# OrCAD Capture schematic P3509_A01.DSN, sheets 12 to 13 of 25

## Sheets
12 0013_USB3.1 HUB: size Custom
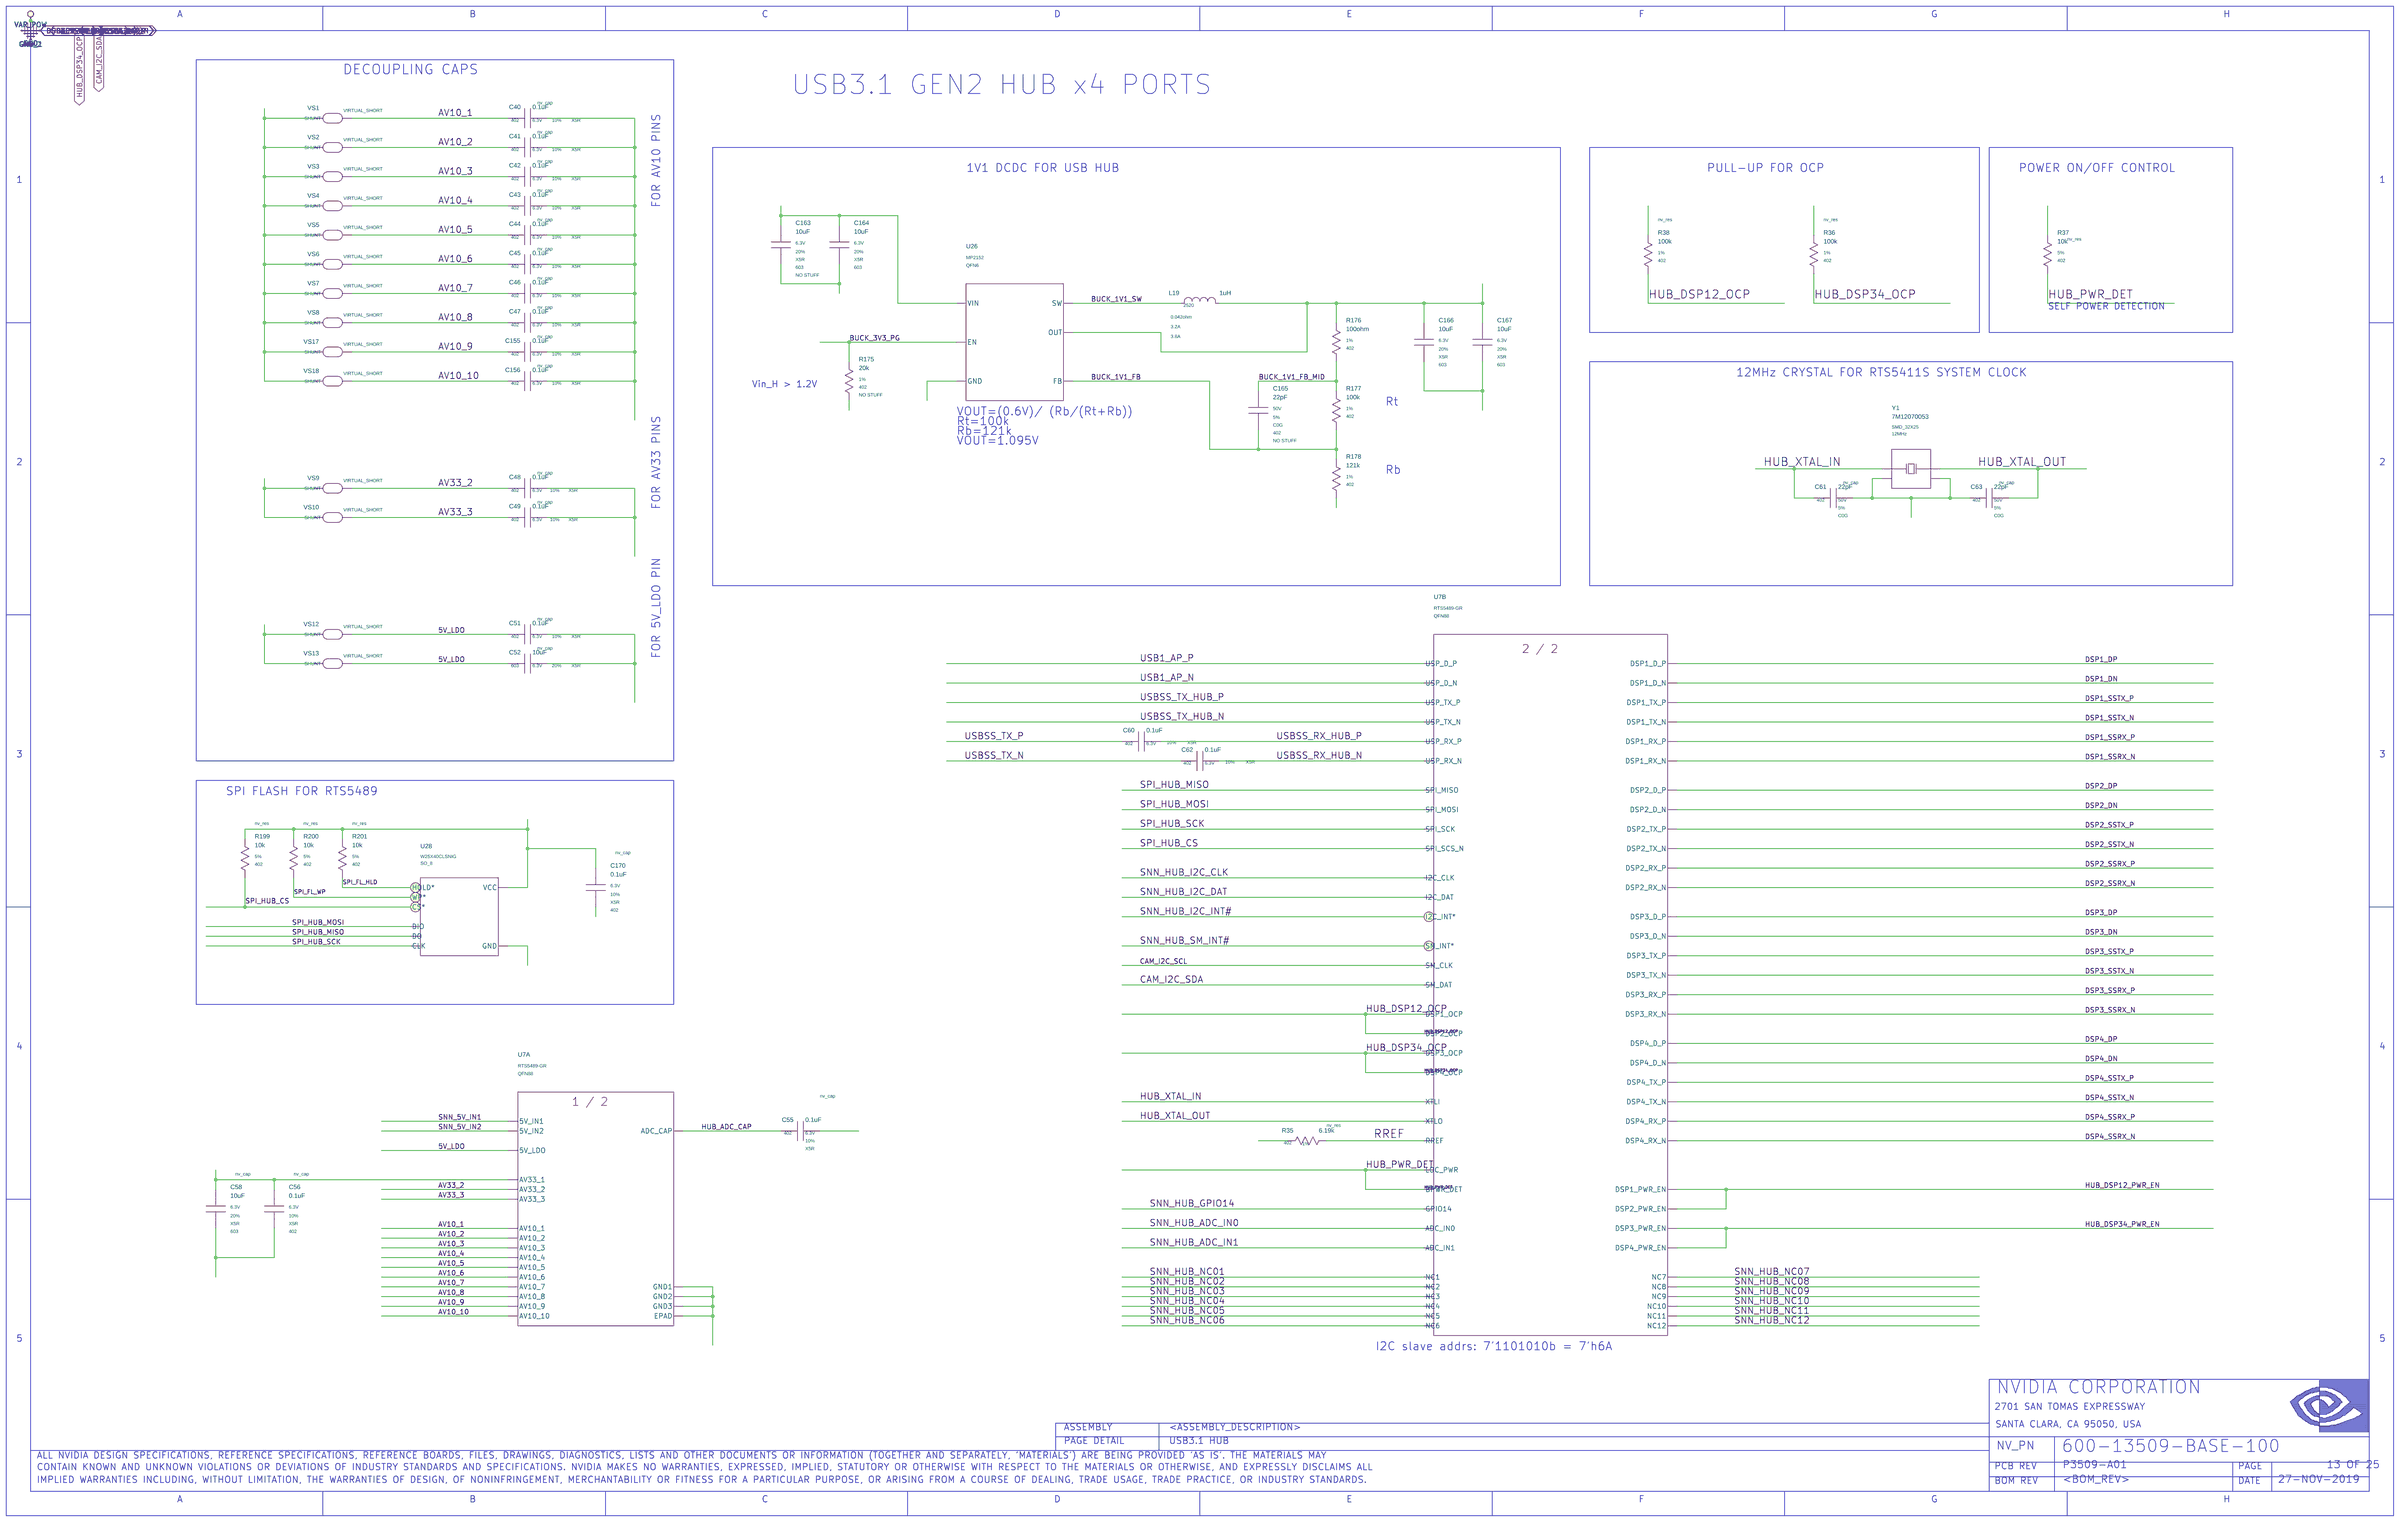
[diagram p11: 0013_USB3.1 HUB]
13 0012_MICRO USB2.0: size Custom
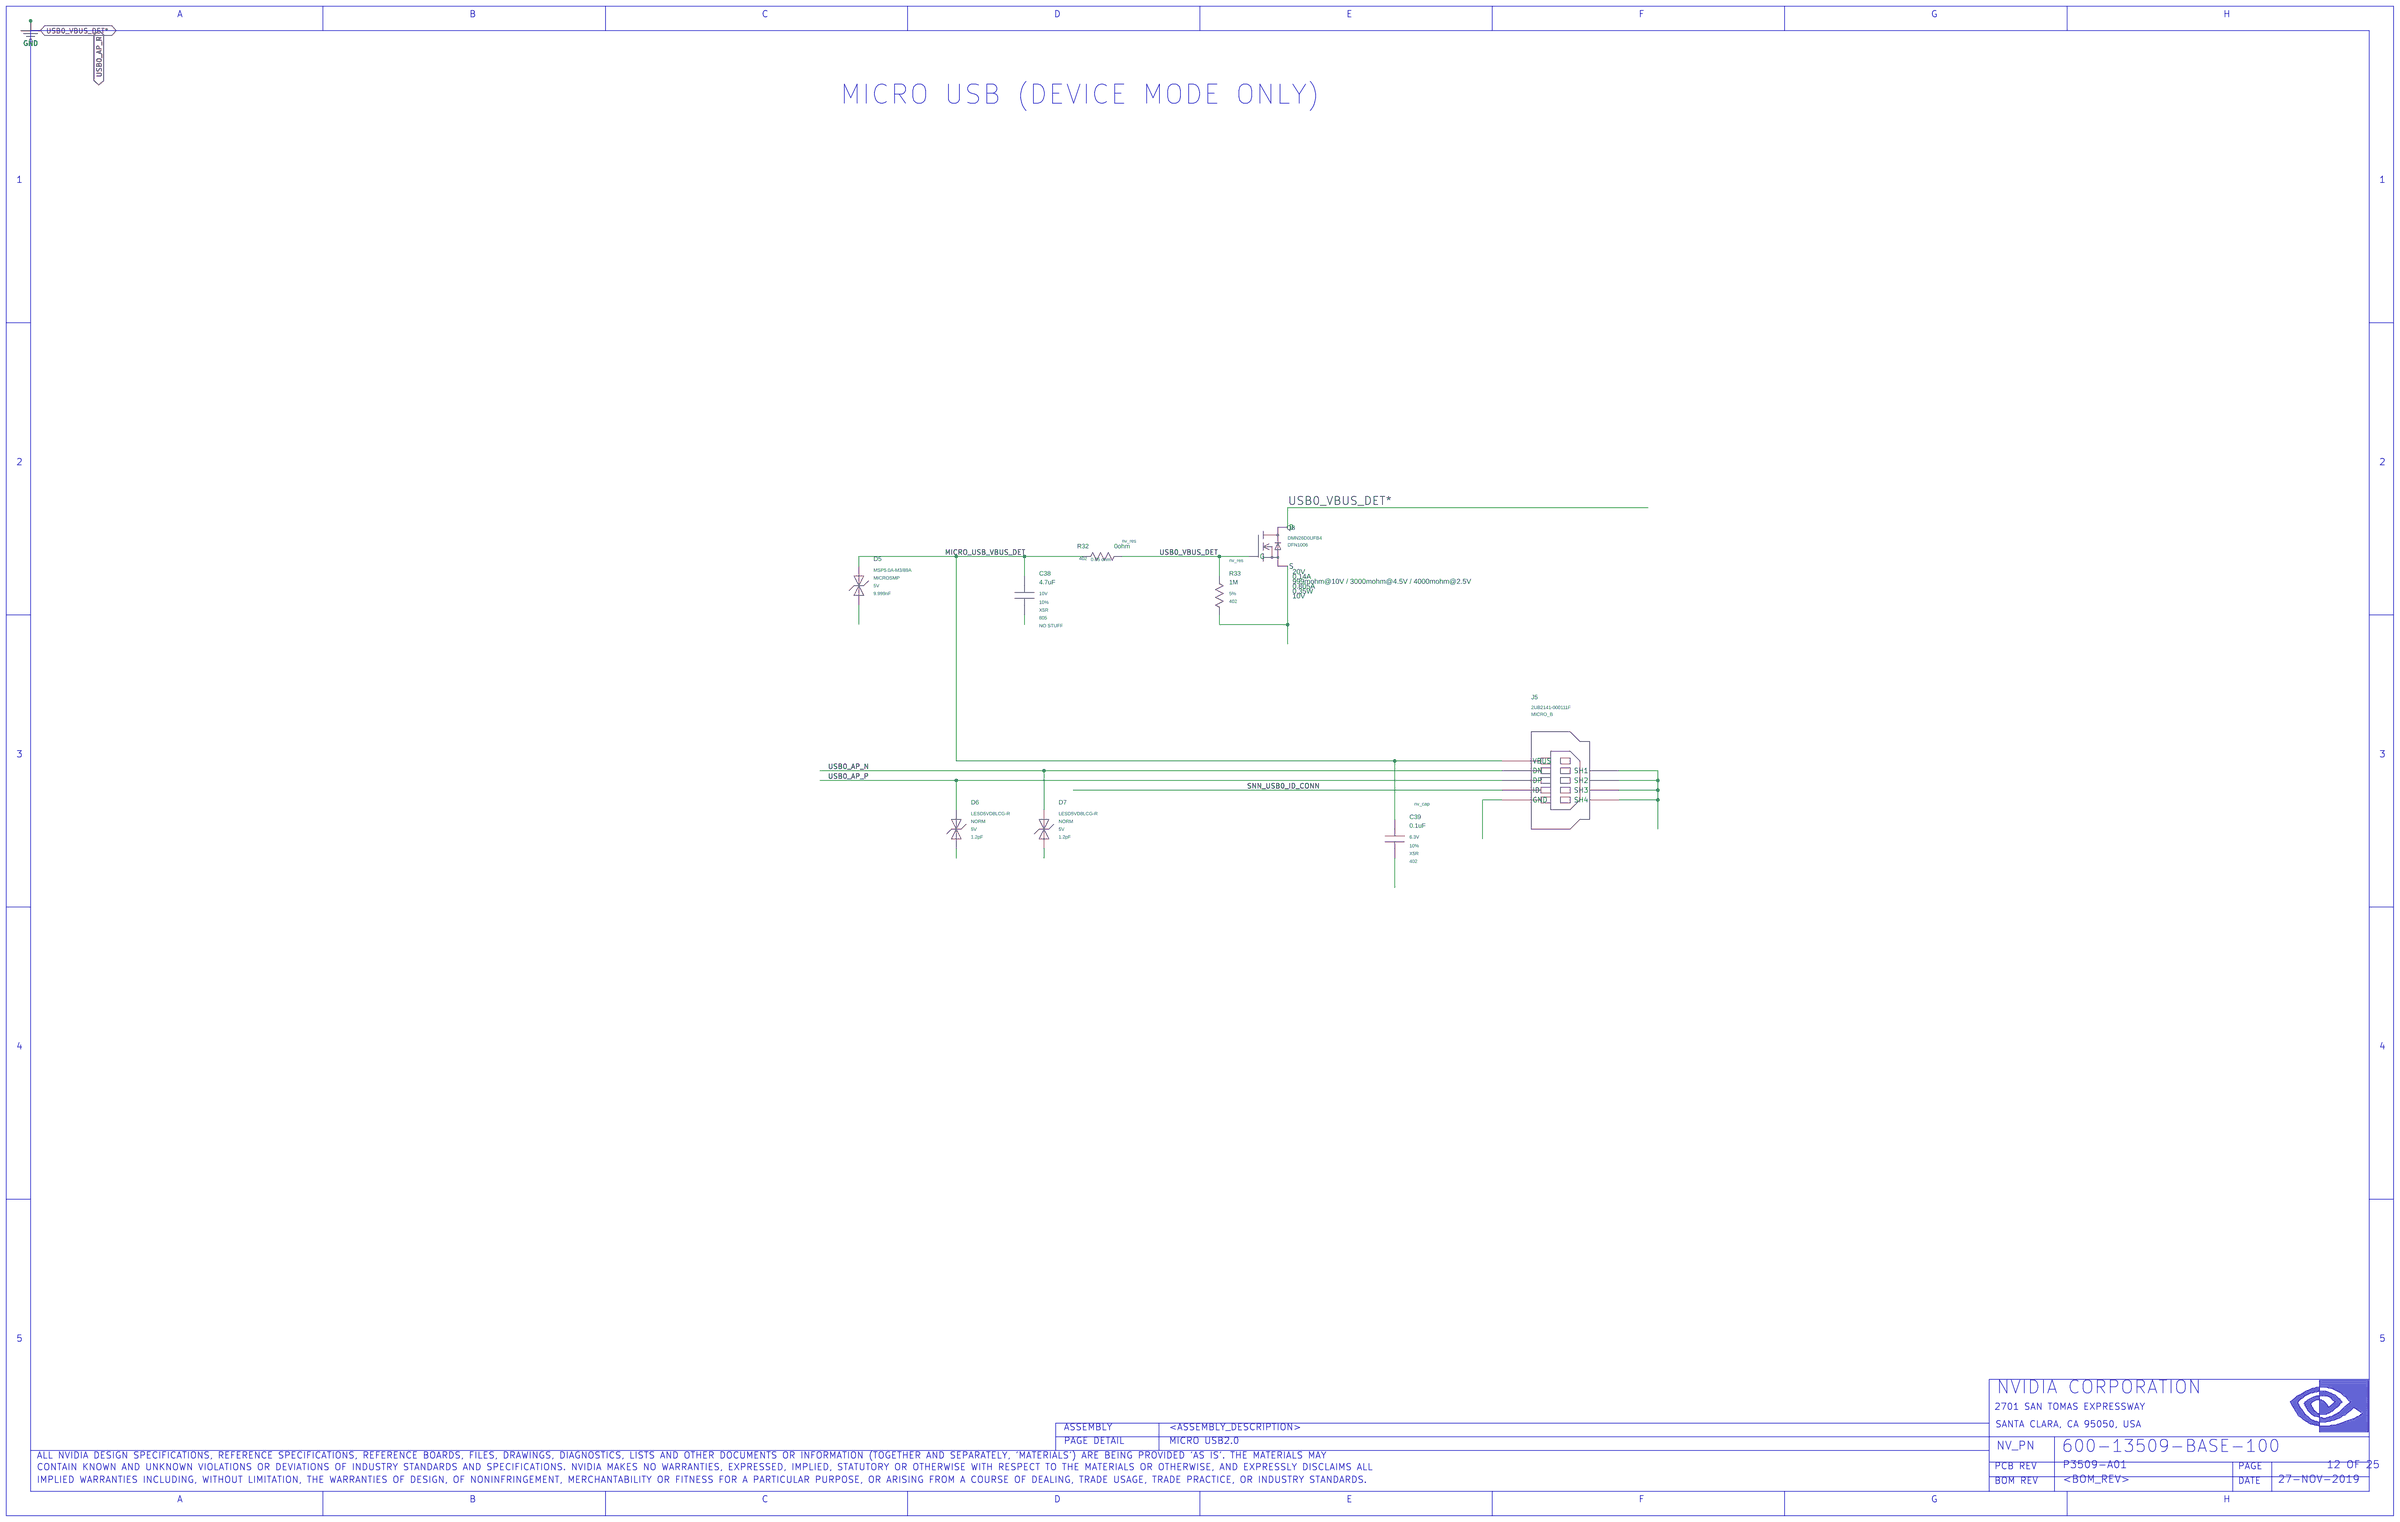
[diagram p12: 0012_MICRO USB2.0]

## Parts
sheet 0012_MICRO USB2.0
C38  4.7uF  [805]
C39  0.1uF  [402]
D5  D_ESD  [DIODE_SMD_025X013]
D6  D_ESD  [DIODE_SMD_010X060]
D7  D_ESD  [DIODE_SMD_010X060]
J5  CON_USB  [CON_USB_005_SMT_RA_080X066]
Q8  Q_FET_N_ENH  [DFET_003_SMD_010X006_B]
R32  0ohm  [402]
R33  1M  [402]
sheet 0013_USB3.1 HUB
C40  0.1uF  [402]
C41  0.1uF  [402]
C42  0.1uF  [402]
C43  0.1uF  [402]
C44  0.1uF  [402]
C45  0.1uF  [402]
C46  0.1uF  [402]
C47  0.1uF  [402]
C48  0.1uF  [402]
C49  0.1uF  [402]
C51  0.1uF  [402]
C52  10uF  [603]
C55  0.1uF  [402]
C56  0.1uF  [402]
C58  10uF  [603]
C60  0.1uF  [402]
C61  22pF  [402]
C62  0.1uF  [402]
C63  22pF  [402]
C155  0.1uF  [402]
C156  0.1uF  [402]
C163  10uF  [603]
C164  10uF  [603]
C165  22pF  [402]
C166  10uF  [603]
C167  10uF  [603]
C170  0.1uF  [402]
L19  1uH  [IND_NONRKO_SMD_025X020]
R35  6.19k  [402]
R36  100k  [402]
R37  10k  [402]
R38  100k  [402]
R175  20k  [402]
R176  100ohm  [402]
R177  100k  [402]
R178  121k  [402]
R199  10k  [402]
R200  10k  [402]
R201  10k  [402]
U7  U_USB_HUB_RTS5489  [QFN088Q_P040_0100_T069X069]  (sections A,B)
U26  0.6V  [DFN06_P050_016X012]
U28  U_MEM_FL_SER_512KX8  [SO08_048X038]
VS1  VIRTUAL_SHORT  [VIRTUAL_SHORT]
VS2  VIRTUAL_SHORT  [VIRTUAL_SHORT]
VS3  VIRTUAL_SHORT  [VIRTUAL_SHORT]
VS4  VIRTUAL_SHORT  [VIRTUAL_SHORT]
VS5  VIRTUAL_SHORT  [VIRTUAL_SHORT]
VS6  VIRTUAL_SHORT  [VIRTUAL_SHORT]
VS7  VIRTUAL_SHORT  [VIRTUAL_SHORT]
VS8  VIRTUAL_SHORT  [VIRTUAL_SHORT]
VS9  VIRTUAL_SHORT  [VIRTUAL_SHORT]
VS10  VIRTUAL_SHORT  [VIRTUAL_SHORT]
VS12  VIRTUAL_SHORT  [VIRTUAL_SHORT]
VS13  VIRTUAL_SHORT  [VIRTUAL_SHORT]
VS17  VIRTUAL_SHORT  [VIRTUAL_SHORT]
VS18  VIRTUAL_SHORT  [VIRTUAL_SHORT]
Y1  12MHz  [XTAL_SMD_4_032X025_D]

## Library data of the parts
C38 = C#1_v2: ASSEMBLY: MICRO_USB; CDS_LIB: discrete; CDS_PART_NAME: C_0805-4.7UF,X5R,10%,10V,039-0152-000; CDS_PHYS_PART_NAME: C_0805-4.7UF,X5R,10%,10V,039-0152-000-039-0152-000,4.7UF; CDS_SEC: 1; CHIPS_PART_NAME: C; DEVICE_TYPENAME: C_0805-47UFX5R1010V039-0152-000-039-0152-00047UF; DRAWING: #NAME?; MAT: X5R; MAX_VOLTAGE: 10V; NV_PN: 039-0152-000; PATH: I14; PHYS_PAGE: 12; ROT: 0; SEC: 1; SIGNAL_MODEL: nv_cap; SKU: NO STUFF; TOL: 10%; VER: 1; XY: (-6900,4600)
C39 = C#1_v2: ASSEMBLY: USBC_PWR; CDS_LIB: discrete; CDS_PART_NAME: C_0402-0.1UF,X5R,10%,6.3V,039-0007-000; CDS_PHYS_PART_NAME: C_0402-0.1UF,X5R,10%,6.3V,039-0007-000-0.1UF,039-0007-000; CDS_SEC: 1; CHIPS_PART_NAME: C; DEVICE_TYPENAME: C_0402-01UFX5R1063V039-0007-000-01UF039-0007-000; DRAWING: #NAME?; MAT: X5R; MAX_VOLTAGE: 6.3V; NV_PN: 039-0007-000; PATH: I20; PHYS_PAGE: 12; ROT: 0; SEC: 1; SIGNAL_MODEL: nv_cap; TOL: 10%; VER: 1; XY: (-5000,3350)
D5 = D_ESD: ASSEMBLY: MICRO_USB; BREAKDOWN_VOLTAGE_MIN_TYP: 6.4V; CAPACITANCE_MAX_TYP: 9.999nF; CDS_LIB: discrete; CDS_PART_NAME: D_ESD_MICROSMP-MSP5.0A-M3/89A,1 LINE,UNI-DIRECTIONAL,5V,100UA,6.4V,9.2V@16.3A,9.999NF,090-0233-000; CDS_PHYS_PART_NAME: D_ESD_MICROSMP-MSP5.0A-M3/89A,1 LINE,UNI-DIRECTIONAL,5V,100UA,6.4V,9.2V@16.3A,9.999NF,090-0233-000-090-0233-000; CDS_SEC: 1; CLAMPING_VOLTAGE: 9.2V@16.3A; CONFIGURATION: 1 Line; DEVICE_TYPENAME: D_ESD_MICROSMP-MSP50A-M389A1LINEUNI-DIRECTIONAL5V100UA64V92V163A9999NF090-0233-000-090-0233-000; DRAWING: #NAME?; MAX_REVERSE_LEAKAGE_CURRENT: 100uA; MAX_REVERSE_VOLTAGE: 5V; NV_NAME: MSP5.0A-M3/89A; NV_PN: 090-0233-000; PACK_TYPE: MICROSMP; PATH: I25; PHYS_PAGE: 12; POLARITY: Uni-Directional; ROT: 0; SEC: 1; VER: 2; XY: (-7750,4650)
D6 = D_ESD: ASSEMBLY: MICRO_USB; BREAKDOWN_VOLTAGE_MIN_TYP: 5.5V; CAPACITANCE_MAX_TYP: 1.2pF; CDS_LIB: discrete; CDS_PART_NAME: D_ESD_NORM-LESD5VD8LCG-R,1 LINE,BI-DIRECTIONAL,5V,0.05UA,5.5V,10V@2A,1.2PF,090-0172-000; CDS_PHYS_PART_NAME: D_ESD_NORM-LESD5VD8LCG-R,1 LINE,BI-DIRECTIONAL,5V,0.05UA,5.5V,10V@2A,1.2PF,090-0172-000-090-0172-000; CDS_SEC: 1; CLAMPING_VOLTAGE: 10V@2A; CONFIGURATION: 1 Line; DEVICE_TYPENAME: D_ESD_NORM-LESD5VD8LCG-R1LINEBI-DIRECTIONAL5V005UA55V10V2A12PF090-0172-000-090-0172-000; DRAWING: #NAME?; MAX_REVERSE_LEAKAGE_CURRENT: 0.05uA; MAX_REVERSE_VOLTAGE: 5V; NV_NAME: LESD5VD8LCG-R; NV_PN: 090-0172-000; PACK_TYPE: NORM; PATH: I18; PHYS_PAGE: 12; POLARITY: Bi-Directional; ROT: 0; SEC: 1; VER: 2; XY: (-7250,3400)
D7 = D_ESD: ASSEMBLY: MICRO_USB; BREAKDOWN_VOLTAGE_MIN_TYP: 5.5V; CAPACITANCE_MAX_TYP: 1.2pF; CDS_LIB: discrete; CDS_PART_NAME: D_ESD_NORM-LESD5VD8LCG-R,1 LINE,BI-DIRECTIONAL,5V,0.05UA,5.5V,10V@2A,1.2PF,090-0172-000; CDS_PHYS_PART_NAME: D_ESD_NORM-LESD5VD8LCG-R,1 LINE,BI-DIRECTIONAL,5V,0.05UA,5.5V,10V@2A,1.2PF,090-0172-000-090-0172-000; CDS_SEC: 1; CLAMPING_VOLTAGE: 10V@2A; CONFIGURATION: 1 Line; DEVICE_TYPENAME: D_ESD_NORM-LESD5VD8LCG-R1LINEBI-DIRECTIONAL5V005UA55V10V2A12PF090-0172-000-090-0172-000; DRAWING: #NAME?; MAX_REVERSE_LEAKAGE_CURRENT: 0.05uA; MAX_REVERSE_VOLTAGE: 5V; NV_NAME: LESD5VD8LCG-R; NV_PN: 090-0172-000; PACK_TYPE: NORM; PATH: I17; PHYS_PAGE: 12; POLARITY: Bi-Directional; ROT: 0; SEC: 1; VER: 2; XY: (-6800,3400)
J5 = CON_USB: ANGLE: 90; ASSEMBLY: MICRO_USB; CDS_LIB: electro_mechanic; CDS_PART_NAME: CON_USB_MICRO_B-2UB2141-000111F,FEMALE,0.65,90,YES,YES,YES,NO,YES,500.0 V,500.0 MA,080-1368-000; CDS_PHYS_PART_NAME: CON_USB_MICRO_B-2UB2141-000111F,FEMALE,0.65,90,YES,YES,YES,NO,YES,500.0 V,500.0 MA,080-1368-000-080-1368-000; CDS_SEC: 1; DEVICE_TYPENAME: CON_USB_MICRO_B-2UB2141-000111FFEMALE06590YESYESYESNOYES5000V5000MA080-1368-000-080-1368-000; DRAWING: #NAME?; EMI_GROUND_TAB: NO; GENDER: FEMALE; LATCHING: YES; MAX_CURRENT: 500.0 mA; MAX_VOLTAGE: 500.0 V; NV_NAME: 2UB2141-000111F; NV_PN: 080-1368-000; PACK_TYPE: MICRO_B; PATH: I4; PHYS_PAGE: 12; PITCH: 0.65; PLACEMENT_NOTE: COLAYOUT WITH J47; REFLOW: YES; ROT: 0; SEC: 1; SHIELDED: YES; SHROUDED: YES; VER: 2; XY: (-4150,3650)
Q8 = Q_FET_N_ENH#1: ASSEMBLY: MICRO_USB; CDS_LIB: discrete; CDS_PART_NAME: Q_FET_N_ENH_DFN1006-DMN26D0UFB4,20V,999MOHM@10V / 3000MOHM@4.5V / 4000MOHM@2.5V,0.14A,0.805A,10V,0.35W,999NC@10V / 0NC@4.5V / A; CDS_PHYS_PART_NAME: Q_FET_N_ENH_DFN1006-DMN26D0UFB4,20V,999MOHM@10V / 3000MOHM@4.5V / 4000MOHM@2.5V,0.14A,0.805A,10V,0.35W,999NC@10V / 0NC@4.5V / B; CDS_SEC: 1; CONTINUOUS_CURRENT: 0.14A; CaptureCellPackProp: Q_FET_N_ENH##1; DEVICE_TYPENAME: Q_FET_N_ENH_DFN1006-DMN26D0UFB420V999MOHM10V3000MOHM45V4000MOHM25V014A0805A10V035W999NC10V0NC45VB; DRAWING: #NAME?; MAX_CURRENT: 0.805A; MAX_VOLTAGE: 20V; MAX_WATTAGE: 0.35W; NV_NAME: DMN26D0UFB4; NV_PN: 300-0868-000; PACK_TYPE: DFN1006; PATH: I10; PHYS_PAGE: 12; Q_G: 999nC@10V / 0nC@4.5V / 999nC@2.5V; ROT: 0; R_DS_ON: 999mohm@10V / 3000mohm@4.5V / 4000mohm@2.5V; SEC: 1; VER: 2; V_BE_GS: 10V; XY: (-5650,4850)
R32 = R#1: ASSEMBLY: MICRO_USB; CDS_LIB: discrete; CDS_PART_NAME: R_0402-0OHM,0.05 OHM,62.5MW,195-2655-000; CDS_PHYS_PART_NAME: R_0402-0OHM,0.05 OHM,62.5MW,195-2655-000-0OHM,195-2655-000; CDS_SEC: 1; CHIPS_PART_NAME: R; DEVICE_TYPENAME: R_0402-0OHM005OHM625MW195-2655-000-0OHM195-2655-000; DRAWING: #NAME?; MAX_WATTAGE: 62.5mW; NV_PN: 195-2655-000; PATH: I13; PHYS_PAGE: 12; ROT: 0; SEC: 1; SIGNAL_MODEL: nv_res; TOL: 0.05 ohm; VER: 1; XY: (-6500,4800)
R33 = R: ASSEMBLY: MICRO_USB; CDS_LIB: discrete; CDS_PART_NAME: R_0402-1M,5 %,62.5MW,195-0488-000; CDS_PHYS_PART_NAME: R_0402-1M,5 %,62.5MW,195-0488-000-195-0488-000,1M; CDS_SEC: 1; DEVICE_TYPENAME: R_0402-1M5625MW195-0488-000-195-0488-0001M; DRAWING: #NAME?; MAX_WATTAGE: 62.5mW; NV_PN: 195-0488-000; PATH: I11; PHYS_PAGE: 12; ROT: 0; SEC: 1; SIGNAL_MODEL: nv_res; TOL: 5%; VER: 2; XY: (-5900,4600)
C40 = C: ASSEMBLY: USB3_TYPEA; CDS_LIB: discrete; CDS_PART_NAME: C_0402-0.1UF,X5R,10%,6.3V,039-0007-000; CDS_PHYS_PART_NAME: C_0402-0.1UF,X5R,10%,6.3V,039-0007-000-0.1UF,039-0007-000; CDS_SEC: 1; DEVICE_TYPENAME: C_0402-01UFX5R1063V039-0007-000-01UF039-0007-000; DRAWING: #NAME?; MAT: X5R; MAX_VOLTAGE: 6.3V; NV_PN: 039-0007-000; PATH: I63; PHYS_PAGE: 13; ROT: 0; SEC: 1; SIGNAL_MODEL: nv_cap; TOL: 10%; VER: 2; XY: (-9450,7050)
C41 = C: ASSEMBLY: USB3_TYPEA; CDS_LIB: discrete; CDS_PART_NAME: C_0402-0.1UF,X5R,10%,6.3V,039-0007-000; CDS_PHYS_PART_NAME: C_0402-0.1UF,X5R,10%,6.3V,039-0007-000-0.1UF,039-0007-000; CDS_SEC: 1; DEVICE_TYPENAME: C_0402-01UFX5R1063V039-0007-000-01UF039-0007-000; DRAWING: #NAME?; MAT: X5R; MAX_VOLTAGE: 6.3V; NV_PN: 039-0007-000; PATH: I64; PHYS_PAGE: 13; ROT: 0; SEC: 1; SIGNAL_MODEL: nv_cap; TOL: 10%; VER: 2; XY: (-9450,6900)
C42 = C: ASSEMBLY: USB3_TYPEA; CDS_LIB: discrete; CDS_PART_NAME: C_0402-0.1UF,X5R,10%,6.3V,039-0007-000; CDS_PHYS_PART_NAME: C_0402-0.1UF,X5R,10%,6.3V,039-0007-000-0.1UF,039-0007-000; CDS_SEC: 1; DEVICE_TYPENAME: C_0402-01UFX5R1063V039-0007-000-01UF039-0007-000; DRAWING: #NAME?; MAT: X5R; MAX_VOLTAGE: 6.3V; NV_PN: 039-0007-000; PATH: I65; PHYS_PAGE: 13; ROT: 0; SEC: 1; SIGNAL_MODEL: nv_cap; TOL: 10%; VER: 2; XY: (-9450,6750)
C43 = C: ASSEMBLY: USB3_TYPEA; CDS_LIB: discrete; CDS_PART_NAME: C_0402-0.1UF,X5R,10%,6.3V,039-0007-000; CDS_PHYS_PART_NAME: C_0402-0.1UF,X5R,10%,6.3V,039-0007-000-0.1UF,039-0007-000; CDS_SEC: 1; DEVICE_TYPENAME: C_0402-01UFX5R1063V039-0007-000-01UF039-0007-000; DRAWING: #NAME?; MAT: X5R; MAX_VOLTAGE: 6.3V; NV_PN: 039-0007-000; PATH: I67; PHYS_PAGE: 13; ROT: 0; SEC: 1; SIGNAL_MODEL: nv_cap; TOL: 10%; VER: 2; XY: (-9450,6600)
C44 = C: ASSEMBLY: USB3_TYPEA; CDS_LIB: discrete; CDS_PART_NAME: C_0402-0.1UF,X5R,10%,6.3V,039-0007-000; CDS_PHYS_PART_NAME: C_0402-0.1UF,X5R,10%,6.3V,039-0007-000-0.1UF,039-0007-000; CDS_SEC: 1; DEVICE_TYPENAME: C_0402-01UFX5R1063V039-0007-000-01UF039-0007-000; DRAWING: #NAME?; MAT: X5R; MAX_VOLTAGE: 6.3V; NV_PN: 039-0007-000; PATH: I66; PHYS_PAGE: 13; ROT: 0; SEC: 1; SIGNAL_MODEL: nv_cap; TOL: 10%; VER: 2; XY: (-9450,6450)
C45 = C: ASSEMBLY: USB3_TYPEA; CDS_LIB: discrete; CDS_PART_NAME: C_0402-0.1UF,X5R,10%,6.3V,039-0007-000; CDS_PHYS_PART_NAME: C_0402-0.1UF,X5R,10%,6.3V,039-0007-000-0.1UF,039-0007-000; CDS_SEC: 1; DEVICE_TYPENAME: C_0402-01UFX5R1063V039-0007-000-01UF039-0007-000; DRAWING: #NAME?; MAT: X5R; MAX_VOLTAGE: 6.3V; NV_PN: 039-0007-000; PATH: I70; PHYS_PAGE: 13; ROT: 0; SEC: 1; SIGNAL_MODEL: nv_cap; TOL: 10%; VER: 2; XY: (-9450,6300)
C46 = C: ASSEMBLY: USB3_TYPEA; CDS_LIB: discrete; CDS_PART_NAME: C_0402-0.1UF,X5R,10%,6.3V,039-0007-000; CDS_PHYS_PART_NAME: C_0402-0.1UF,X5R,10%,6.3V,039-0007-000-0.1UF,039-0007-000; CDS_SEC: 1; DEVICE_TYPENAME: C_0402-01UFX5R1063V039-0007-000-01UF039-0007-000; DRAWING: #NAME?; MAT: X5R; MAX_VOLTAGE: 6.3V; NV_PN: 039-0007-000; PATH: I71; PHYS_PAGE: 13; ROT: 0; SEC: 1; SIGNAL_MODEL: nv_cap; TOL: 10%; VER: 2; XY: (-9450,6150)
C47 = C: ASSEMBLY: USB3_TYPEA; CDS_LIB: discrete; CDS_PART_NAME: C_0402-0.1UF,X5R,10%,6.3V,039-0007-000; CDS_PHYS_PART_NAME: C_0402-0.1UF,X5R,10%,6.3V,039-0007-000-0.1UF,039-0007-000; CDS_SEC: 1; DEVICE_TYPENAME: C_0402-01UFX5R1063V039-0007-000-01UF039-0007-000; DRAWING: #NAME?; MAT: X5R; MAX_VOLTAGE: 6.3V; NV_PN: 039-0007-000; PATH: I72; PHYS_PAGE: 13; ROT: 0; SEC: 1; SIGNAL_MODEL: nv_cap; TOL: 10%; VER: 2; XY: (-9450,6000)
C48 = C: ASSEMBLY: USB3_TYPEA; CDS_LIB: discrete; CDS_PART_NAME: C_0402-0.1UF,X5R,10%,6.3V,039-0007-000; CDS_PHYS_PART_NAME: C_0402-0.1UF,X5R,10%,6.3V,039-0007-000-0.1UF,039-0007-000; CDS_SEC: 1; DEVICE_TYPENAME: C_0402-01UFX5R1063V039-0007-000-01UF039-0007-000; DRAWING: #NAME?; MAT: X5R; MAX_VOLTAGE: 6.3V; NV_PN: 039-0007-000; PATH: I73; PHYS_PAGE: 13; ROT: 0; SEC: 1; SIGNAL_MODEL: nv_cap; TOL: 10%; VER: 2; XY: (-9450,5150)
C49 = C: ASSEMBLY: USB3_TYPEA; CDS_LIB: discrete; CDS_PART_NAME: C_0402-0.1UF,X5R,10%,6.3V,039-0007-000; CDS_PHYS_PART_NAME: C_0402-0.1UF,X5R,10%,6.3V,039-0007-000-0.1UF,039-0007-000; CDS_SEC: 1; DEVICE_TYPENAME: C_0402-01UFX5R1063V039-0007-000-01UF039-0007-000; DRAWING: #NAME?; MAT: X5R; MAX_VOLTAGE: 6.3V; NV_PN: 039-0007-000; PATH: I74; PHYS_PAGE: 13; ROT: 0; SEC: 1; SIGNAL_MODEL: nv_cap; TOL: 10%; VER: 2; XY: (-9450,5000)
C51 = C: ASSEMBLY: USB3_TYPEA; CDS_LIB: discrete; CDS_PART_NAME: C_0402-0.1UF,X5R,10%,6.3V,039-0007-000; CDS_PHYS_PART_NAME: C_0402-0.1UF,X5R,10%,6.3V,039-0007-000-0.1UF,039-0007-000; CDS_SEC: 1; DEVICE_TYPENAME: C_0402-01UFX5R1063V039-0007-000-01UF039-0007-000; DRAWING: #NAME?; MAT: X5R; MAX_VOLTAGE: 6.3V; NV_PN: 039-0007-000; PATH: I77; PHYS_PAGE: 13; ROT: 0; SEC: 1; SIGNAL_MODEL: nv_cap; TOL: 10%; VER: 2; XY: (-9450,4400)
C52 = C: ASSEMBLY: USB3_TYPEA; CDS_LIB: discrete; CDS_PART_NAME: C_0603-10UF,X5R,20%,6.3V,039-0135-000; CDS_PHYS_PART_NAME: C_0603-10UF,X5R,20%,6.3V,039-0135-000-039-0135-000,10UF; CDS_SEC: 1; DEVICE_TYPENAME: C_0603-10UFX5R2063V039-0135-000-039-0135-00010UF; DRAWING: #NAME?; MAT: X5R; MAX_VOLTAGE: 6.3V; NV_PN: 039-0135-000; PATH: I76; PHYS_PAGE: 13; ROT: 0; SEC: 1; SIGNAL_MODEL: nv_cap; TOL: 20%; VER: 2; XY: (-9450,4250)
C55 = C: ASSEMBLY: USB3_TYPEA; CDS_LIB: discrete; CDS_PART_NAME: C_0402-0.1UF,X5R,10%,6.3V,039-0007-000; CDS_PHYS_PART_NAME: C_0402-0.1UF,X5R,10%,6.3V,039-0007-000-0.1UF,039-0007-000; CDS_SEC: 1; DEVICE_TYPENAME: C_0402-01UFX5R1063V039-0007-000-01UF039-0007-000; DRAWING: #NAME?; MAT: X5R; MAX_VOLTAGE: 6.3V; NV_PN: 039-0007-000; PATH: I100; PHYS_PAGE: 13; ROT: 0; SEC: 1; SIGNAL_MODEL: nv_cap; TOL: 10%; VER: 2; XY: (-8050,1850)
C56 = C#1_v2: ASSEMBLY: USB3_TYPEA; CDS_LIB: discrete; CDS_PART_NAME: C_0402-0.1UF,X5R,10%,6.3V,039-0007-000; CDS_PHYS_PART_NAME: C_0402-0.1UF,X5R,10%,6.3V,039-0007-000-0.1UF,039-0007-000; CDS_SEC: 1; CHIPS_PART_NAME: C; DEVICE_TYPENAME: C_0402-01UFX5R1063V039-0007-000-01UF039-0007-000; DRAWING: #NAME?; MAT: X5R; MAX_VOLTAGE: 6.3V; NV_PN: 039-0007-000; PATH: I105; PHYS_PAGE: 13; ROT: 0; SEC: 1; SIGNAL_MODEL: nv_cap; TOL: 10%; VER: 1; XY: (-10750,1450)
C58 = C#1_v2: ASSEMBLY: USB3_TYPEA; CDS_LIB: discrete; CDS_PART_NAME: C_0603-10UF,X5R,20%,6.3V,039-0135-000; CDS_PHYS_PART_NAME: C_0603-10UF,X5R,20%,6.3V,039-0135-000-039-0135-000,10UF; CDS_SEC: 1; CHIPS_PART_NAME: C; DEVICE_TYPENAME: C_0603-10UFX5R2063V039-0135-000-039-0135-00010UF; DRAWING: #NAME?; MAT: X5R; MAX_VOLTAGE: 6.3V; NV_PN: 039-0135-000; PATH: I102; PHYS_PAGE: 13; ROT: 0; SEC: 1; SIGNAL_MODEL: nv_cap; TOL: 20%; VER: 1; XY: (-11050,1450)
C60 = C: ASSEMBLY: USB3_TYPEA; CDS_LIB: discrete; CDS_PART_NAME: C_0402-0.1UF,X5R,10%,6.3V,039-0007-000; CDS_PHYS_PART_NAME: C_0402-0.1UF,X5R,10%,6.3V,039-0007-000-0.1UF,039-0007-000; CDS_SEC: 1; DEVICE_TYPENAME: C_0402-01UFX5R1063V039-0007-000-01UF039-0007-000; DRAWING: #NAME?; MAT: X5R; MAX_VOLTAGE: 6.3V; NV_PN: 039-0007-000; PATH: I138; PHYS_PAGE: 13; ROT: 0; SEC: 1; SIGNAL_MODEL: nv_cap; TOL: 10%; VER: 2; XY: (-6300,3850)
C61 = C: ASSEMBLY: USB3_TYPEA; CDS_LIB: discrete; CDS_PART_NAME: C_0402-22PF,C0G,5%,50V,035-0023-000; CDS_PHYS_PART_NAME: C_0402-22PF,C0G,5%,50V,035-0023-000-035-0023-000,22PF; CDS_SEC: 1; DEVICE_TYPENAME: C_0402-22PFC0G550V035-0023-000-035-0023-00022PF; DRAWING: #NAME?; MAT: C0G; MAX_VOLTAGE: 50V; NV_PN: 035-0023-000; PATH: I15; PHYS_PAGE: 13; ROT: 0; SEC: 1; SIGNAL_MODEL: nv_cap; TOL: 5%; VER: 2; XY: (-2750,5100)
C62 = C: ASSEMBLY: USB3_TYPEA; CDS_LIB: discrete; CDS_PART_NAME: C_0402-0.1UF,X5R,10%,6.3V,039-0007-000; CDS_PHYS_PART_NAME: C_0402-0.1UF,X5R,10%,6.3V,039-0007-000-0.1UF,039-0007-000; CDS_SEC: 1; DEVICE_TYPENAME: C_0402-01UFX5R1063V039-0007-000-01UF039-0007-000; DRAWING: #NAME?; MAT: X5R; MAX_VOLTAGE: 6.3V; NV_PN: 039-0007-000; PATH: I137; PHYS_PAGE: 13; ROT: 0; SEC: 1; SIGNAL_MODEL: nv_cap; TOL: 10%; VER: 2; XY: (-6000,3750)
C63 = C: ASSEMBLY: USB3_TYPEA; CDS_LIB: discrete; CDS_PART_NAME: C_0402-22PF,C0G,5%,50V,035-0023-000; CDS_PHYS_PART_NAME: C_0402-22PF,C0G,5%,50V,035-0023-000-035-0023-000,22PF; CDS_SEC: 1; DEVICE_TYPENAME: C_0402-22PFC0G550V035-0023-000-035-0023-00022PF; DRAWING: #NAME?; MAT: C0G; MAX_VOLTAGE: 50V; NV_PN: 035-0023-000; PATH: I11; PHYS_PAGE: 13; ROT: 0; SEC: 1; SIGNAL_MODEL: nv_cap; TOL: 5%; VER: 2; XY: (-1950,5100)
C155 = C: ASSEMBLY: USB3_TYPEA; CDS_LIB: discrete; CDS_PART_NAME: C_0402-0.1UF,X5R,10%,6.3V,039-0007-000; CDS_PHYS_PART_NAME: C_0402-0.1UF,X5R,10%,6.3V,039-0007-000-0.1UF,039-0007-000; CDS_SEC: 1; DEVICE_TYPENAME: C_0402-01UFX5R1063V039-0007-000-01UF039-0007-000; DRAWING: #NAME?; MAT: X5R; MAX_VOLTAGE: 6.3V; NV_PN: 039-0007-000; PATH: I149; PHYS_PAGE: 13; ROT: 0; SEC: 1; SIGNAL_MODEL: nv_cap; TOL: 10%; VER: 2; XY: (-9450,5850)
C156 = C: ASSEMBLY: USB3_TYPEA; CDS_LIB: discrete; CDS_PART_NAME: C_0402-0.1UF,X5R,10%,6.3V,039-0007-000; CDS_PHYS_PART_NAME: C_0402-0.1UF,X5R,10%,6.3V,039-0007-000-0.1UF,039-0007-000; CDS_SEC: 1; DEVICE_TYPENAME: C_0402-01UFX5R1063V039-0007-000-01UF039-0007-000; DRAWING: #NAME?; MAT: X5R; MAX_VOLTAGE: 6.3V; NV_PN: 039-0007-000; PATH: I150; PHYS_PAGE: 13; ROT: 0; SEC: 1; SIGNAL_MODEL: nv_cap; TOL: 10%; VER: 2; XY: (-9450,5700)
C163 = C#1_v2: ASSEMBLY: 1V1_DCDC; CDS_LIB: discrete; CDS_PART_NAME: C_0603-10UF,X5R,20%,6.3V,039-0135-000; CDS_PHYS_PART_NAME: C_0603-10UF,X5R,20%,6.3V,039-0135-000-039-0135-000,10UF; CDS_SEC: 1; CHIPS_PART_NAME: C; DEVICE_TYPENAME: C_0603-10UFX5R2063V039-0135-000-039-0135-00010UF; DRAWING: #NAME?; MAT: X5R; MAX_VOLTAGE: 6.3V; NV_PN: 039-0135-000; PATH: I193; PHYS_PAGE: 13; ROT: 0; SEC: 1; SIGNAL_MODEL: nv_cap; SKU: NO STUFF; TOL: 20%; VER: 1; XY: (-8150,6400)
C164 = C#1_v2: ASSEMBLY: 1V1_DCDC; CDS_LIB: discrete; CDS_PART_NAME: C_0603-10UF,X5R,20%,6.3V,039-0135-000; CDS_PHYS_PART_NAME: C_0603-10UF,X5R,20%,6.3V,039-0135-000-039-0135-000,10UF; CDS_SEC: 1; CHIPS_PART_NAME: C; DEVICE_TYPENAME: C_0603-10UFX5R2063V039-0135-000-039-0135-00010UF; DRAWING: #NAME?; MAT: X5R; MAX_VOLTAGE: 6.3V; NV_PN: 039-0135-000; PATH: I182; PHYS_PAGE: 13; ROT: 0; SEC: 1; SIGNAL_MODEL: nv_cap; TOL: 20%; VER: 1; XY: (-7850,6400)
C165 = C#1_v2: ASSEMBLY: 1V1_DCDC; CDS_LIB: discrete; CDS_PART_NAME: C_0402-22PF,C0G,5%,50V,035-0023-000; CDS_PHYS_PART_NAME: C_0402-22PF,C0G,5%,50V,035-0023-000-035-0023-000,22PF; CDS_SEC: 1; CHIPS_PART_NAME: C; DEVICE_TYPENAME: C_0402-22PFC0G550V035-0023-000-035-0023-00022PF; DRAWING: #NAME?; MAT: C0G; MAX_VOLTAGE: 50V; NV_PN: 035-0023-000; PATH: I189; PHYS_PAGE: 13; ROT: 0; SEC: 1; SIGNAL_MODEL: nv_cap; SKU: NO STUFF; TOL: 5%; VER: 1; XY: (-5700,5550)
C166 = C#1_v2: ASSEMBLY: 1V1_DCDC; CDS_LIB: discrete; CDS_PART_NAME: C_0603-10UF,X5R,20%,6.3V,039-0135-000; CDS_PHYS_PART_NAME: C_0603-10UF,X5R,20%,6.3V,039-0135-000-039-0135-000,10UF; CDS_SEC: 1; CHIPS_PART_NAME: C; DEVICE_TYPENAME: C_0603-10UFX5R2063V039-0135-000-039-0135-00010UF; DRAWING: #NAME?; MAT: X5R; MAX_VOLTAGE: 6.3V; NV_PN: 039-0135-000; PATH: I179; PHYS_PAGE: 13; ROT: 0; SEC: 1; SIGNAL_MODEL: nv_cap; TOL: 20%; VER: 1; XY: (-4850,5900)
C167 = C#1_v2: ASSEMBLY: 1V1_DCDC; CDS_LIB: discrete; CDS_PART_NAME: C_0603-10UF,X5R,20%,6.3V,039-0135-000; CDS_PHYS_PART_NAME: C_0603-10UF,X5R,20%,6.3V,039-0135-000-039-0135-000,10UF; CDS_SEC: 1; CHIPS_PART_NAME: C; DEVICE_TYPENAME: C_0603-10UFX5R2063V039-0135-000-039-0135-00010UF; DRAWING: #NAME?; MAT: X5R; MAX_VOLTAGE: 6.3V; NV_PN: 039-0135-000; PATH: I178; PHYS_PAGE: 13; ROT: 0; SEC: 1; SIGNAL_MODEL: nv_cap; TOL: 20%; VER: 1; XY: (-4550,5900)
C170 = C#1_v2: ASSEMBLY: USB3_TYPEA; CDS_LIB: discrete; CDS_PART_NAME: C_0402-0.1UF,X5R,10%,6.3V,039-0007-000; CDS_PHYS_PART_NAME: C_0402-0.1UF,X5R,10%,6.3V,039-0007-000-0.1UF,039-0007-000; CDS_SEC: 1; CHIPS_PART_NAME: C; DEVICE_TYPENAME: C_0402-01UFX5R1063V039-0007-000-01UF039-0007-000; DRAWING: #NAME?; MAT: X5R; MAX_VOLTAGE: 6.3V; NV_PN: 039-0007-000; PATH: I199; PHYS_PAGE: 13; ROT: 0; SEC: 1; SIGNAL_MODEL: nv_cap; TOL: 10%; VER: 1; XY: (-9100,3100)
L19 = L: ASSEMBLY: 1V1_DCDC; CDS_LIB: discrete; CDS_PART_NAME: L_2520-1UH,METAL ALLOY,20%,3.2A,3.8A,0.042OHM,[ ]@[ ],[ ],130-0562-000; CDS_PHYS_PART_NAME: L_2520-1UH,METAL ALLOY,20%,3.2A,3.8A,0.042OHM,[ ]@[ ],[ ],130-0562-000-130-0562-000,1UH; CDS_SEC: 1; CONTINUOUS_CURRENT: 3.2A; DC_RESISTANCE: 0.042ohm; DEVICE_TYPENAME: L_2520-1UHMETALALLOY2032A38A0042OHM130-0562-000-130-0562-0001UH; DRAWING: #NAME?; MAT: Metal Alloy; MAX_CURRENT: 3.8A; NV_PN: 130-0562-000; PACK_TYPE: 2520; PATH: I181; PHYS_PAGE: 13; Q: [ ]@[ ]; ROT: 0; SEC: 1; SELF_RESONANCE_FREQ: [ ]; SIGNAL_MODEL: nv_ind; TOL: 20%; VER: 1; XY: (-6000,6100)
R35 = R#1: ASSEMBLY: USB3_TYPEA; CDS_LIB: discrete; CDS_PART_NAME: R_0402-6.19K,1 %,62.5MW,195-0384-000; CDS_PHYS_PART_NAME: R_0402-6.19K,1 %,62.5MW,195-0384-000-195-0384-000,6.19K; CDS_SEC: 1; CHIPS_PART_NAME: R; DEVICE_TYPENAME: R_0402-619K1625MW195-0384-000-195-0384-000619K; DRAWING: #NAME?; MAX_WATTAGE: 62.5mW; NV_PN: 195-0384-000; PATH: I139; PHYS_PAGE: 13; ROT: 0; SEC: 1; SIGNAL_MODEL: nv_res; TOL: 1%; VER: 1; XY: (-5450,1800)
R36 = R: ASSEMBLY: USB3_TYPEA; CDS_LIB: discrete; CDS_PART_NAME: R_0402-100K,1 %,62.5MW,195-0005-000; CDS_PHYS_PART_NAME: R_0402-100K,1 %,62.5MW,195-0005-000-100K,195-0005-000; CDS_SEC: 1; DEVICE_TYPENAME: R_0402-100K1625MW195-0005-000-100K195-0005-000; DRAWING: #NAME?; MAX_WATTAGE: 62.5mW; NV_PN: 195-0005-000; PATH: I49; PHYS_PAGE: 13; ROT: 0; SEC: 1; SIGNAL_MODEL: nv_res; TOL: 1%; VER: 2; XY: (-2850,6350)
R37 = R: ASSEMBLY: USB3_TYPEA; CDS_LIB: discrete; CDS_PART_NAME: R_0402-10K,5 %,62.5MW,195-0486-000; CDS_PHYS_PART_NAME: R_0402-10K,5 %,62.5MW,195-0486-000-10K,195-0486-000; CDS_SEC: 1; DEVICE_TYPENAME: R_0402-10K5625MW195-0486-000-10K195-0486-000; DRAWING: #NAME?; MAX_WATTAGE: 62.5mW; NV_PN: 195-0486-000; PATH: I46; PHYS_PAGE: 13; ROT: 0; SEC: 1; SIGNAL_MODEL: nv_res; TOL: 5%; VER: 2; XY: (-1650,6350)
R38 = R: ASSEMBLY: USB3_TYPEA; CDS_LIB: discrete; CDS_PART_NAME: R_0402-100K,1 %,62.5MW,195-0005-000; CDS_PHYS_PART_NAME: R_0402-100K,1 %,62.5MW,195-0005-000-100K,195-0005-000; CDS_SEC: 1; DEVICE_TYPENAME: R_0402-100K1625MW195-0005-000-100K195-0005-000; DRAWING: #NAME?; MAX_WATTAGE: 62.5mW; NV_PN: 195-0005-000; PATH: I166; PHYS_PAGE: 13; ROT: 0; SEC: 1; SIGNAL_MODEL: nv_res; TOL: 1%; VER: 2; XY: (-3700,6350)
R175 = R: ASSEMBLY: 1V1_DCDC; CDS_LIB: discrete; CDS_PART_NAME: R_0402-20K,1 %,62.5MW,195-0150-000; CDS_PHYS_PART_NAME: R_0402-20K,1 %,62.5MW,195-0150-000-195-0150-000,20K; CDS_SEC: 1; DEVICE_TYPENAME: R_0402-20K1625MW195-0150-000-195-0150-00020K; DRAWING: #NAME?; MAX_WATTAGE: 62.5mW; NV_PN: 195-0150-000; PATH: I184; PHYS_PAGE: 13; ROT: 0; SEC: 1; SIGNAL_MODEL: nv_res; SKU: NO STUFF; TOL: 1%; VER: 2; XY: (-7800,5700)
R176 = R: ASSEMBLY: 1V1_DCDC; CDS_LIB: discrete; CDS_PART_NAME: R_0402-100OHM,1 %,62.5MW,195-0002-000; CDS_PHYS_PART_NAME: R_0402-100OHM,1 %,62.5MW,195-0002-000-100OHM,195-0002-000; CDS_SEC: 1; DEVICE_TYPENAME: R_0402-100OHM1625MW195-0002-000-100OHM195-0002-000; DRAWING: #NAME?; MAX_WATTAGE: 62.5mW; NV_PN: 195-0002-000; PATH: I180; PHYS_PAGE: 13; ROT: 0; SEC: 1; SIGNAL_MODEL: nv_res; TOL: 1%; VER: 2; XY: (-5300,5900)
R177 = R: ASSEMBLY: 1V1_DCDC; CDS_LIB: discrete; CDS_PART_NAME: R_0402-100K,1 %,62.5MW,195-0005-000; CDS_PHYS_PART_NAME: R_0402-100K,1 %,62.5MW,195-0005-000-100K,195-0005-000; CDS_SEC: 1; DEVICE_TYPENAME: R_0402-100K1625MW195-0005-000-100K195-0005-000; DRAWING: #NAME?; MAX_WATTAGE: 62.5mW; NV_PN: 195-0005-000; PATH: I186; PHYS_PAGE: 13; ROT: 0; SEC: 1; SIGNAL_MODEL: nv_res; TOL: 1%; VER: 2; XY: (-5300,5550)
R178 = R: ASSEMBLY: 1V1_DCDC; CDS_LIB: discrete; CDS_PART_NAME: R_0402-121K,1 %,62.5MW,195-0046-000; CDS_PHYS_PART_NAME: R_0402-121K,1 %,62.5MW,195-0046-000-121K,195-0046-000; CDS_SEC: 1; DEVICE_TYPENAME: R_0402-121K1625MW195-0046-000-121K195-0046-000; DRAWING: #NAME?; MAX_WATTAGE: 62.5mW; NV_PN: 195-0046-000; PATH: I187; PHYS_PAGE: 13; ROT: 0; SEC: 1; SIGNAL_MODEL: nv_res; TOL: 1%; VER: 2; XY: (-5300,5200)
R199 = R: ASSEMBLY: USB3_TYPEA; CDS_LIB: discrete; CDS_PART_NAME: R_0402-10K,5 %,62.5MW,195-0486-000; CDS_PHYS_PART_NAME: R_0402-10K,5 %,62.5MW,195-0486-000-10K,195-0486-000; CDS_SEC: 1; DEVICE_TYPENAME: R_0402-10K5625MW195-0486-000-10K195-0486-000; DRAWING: #NAME?; MAX_WATTAGE: 62.5mW; NV_PN: 195-0486-000; PATH: I205; PHYS_PAGE: 13; ROT: 0; SEC: 1; SIGNAL_MODEL: nv_res; TOL: 5%; VER: 2; XY: (-10900,3250)
R200 = R: ASSEMBLY: USB3_TYPEA; CDS_LIB: discrete; CDS_PART_NAME: R_0402-10K,5 %,62.5MW,195-0486-000; CDS_PHYS_PART_NAME: R_0402-10K,5 %,62.5MW,195-0486-000-10K,195-0486-000; CDS_SEC: 1; DEVICE_TYPENAME: R_0402-10K5625MW195-0486-000-10K195-0486-000; DRAWING: #NAME?; MAX_WATTAGE: 62.5mW; NV_PN: 195-0486-000; PATH: I204; PHYS_PAGE: 13; ROT: 0; SEC: 1; SIGNAL_MODEL: nv_res; TOL: 5%; VER: 2; XY: (-10650,3250)
R201 = R: ASSEMBLY: USB3_TYPEA; CDS_LIB: discrete; CDS_PART_NAME: R_0402-10K,5 %,62.5MW,195-0486-000; CDS_PHYS_PART_NAME: R_0402-10K,5 %,62.5MW,195-0486-000-10K,195-0486-000; CDS_SEC: 1; DEVICE_TYPENAME: R_0402-10K5625MW195-0486-000-10K195-0486-000; DRAWING: #NAME?; MAX_WATTAGE: 62.5mW; NV_PN: 195-0486-000; PATH: I202; PHYS_PAGE: 13; ROT: 0; SEC: 1; SIGNAL_MODEL: nv_res; TOL: 5%; VER: 2; XY: (-10400,3250)
U7 = U_USB_HUB_RTS5489: ASSEMBLY: USB3_TYPEA; CDS_LIB: digital; CDS_PART_NAME: U_USB_HUB_RTS5489_QFN88-RTS5489-GR,USB,115-2752-000; CDS_PHYS_PART_NAME: U_USB_HUB_RTS5489_QFN88-RTS5489-GR,USB,115-2752-000-115-2752-000; CDS_SEC: 1; CaptureCellPackProp: U_USB_HUB_RTS5489A; DEVICE_TYPENAME: U_USB_HUB_RTS5489_QFN88-RTS5489-GRUSB115-2752-000-115-2752-000; DRAWING: #NAME?; NV_NAME: RTS5489-GR; NV_PN: 115-2752-000; PACK_TYPE: QFN88; PATH: I145; PHYS_PAGE: 13; ROT: 0; SEC: 1; SEC_TYPE: QFN88; TYPE: USB; VER: 1; XY: (-9100,1450)
U26 = U_DCDC_BUCK_MP2152: ASSEMBLY: 1V1_DCDC; CDS_LIB: power_supply; CDS_PART_NAME: U_DCDC_BUCK_MP2152_QFN6-MP2152,BUCK,1PH,1.1MHZ,NONE,0.6V..5.5V,1.5%,0.6V,5.5V,2A,2W,316-0758-000; CDS_PHYS_PART_NAME: U_DCDC_BUCK_MP2152_QFN6-MP2152,BUCK,1PH,1.1MHZ,NONE,0.6V..5.5V,1.5%,0.6V,5.5V,2A,2W,316-0758-000-0.6V,316-0758-000; CDS_SEC: 1; DEVICE_TYPENAME: U_DCDC_BUCK_MP2152_QFN6-MP2152BUCK1PH11MHZNONE06V55V1506V55V2A2W316-0758-000-06V316-0758-000; DRAWING: #NAME?; MAX_CURRENT: 2A; MAX_VOLTAGE: 5.5V; MAX_WATTAGE: 2W; MODE: Buck; NV_NAME: MP2152; NV_PN: 316-0758-000; OUTPUT_VOLTAGE: 0.6V..5.5V; PACK_TYPE: QFN6; PATH: I176; PHASES: 1Ph; PHYS_PAGE: 13; PROGRAMMABLE: None; ROT: 0; SEC: 1; SWITCHING_FREQ: 1.1MHz; TOL: 1.50%; VER: 1; XY: (-6950,5900)
U28 = U_MEM_FL_SER_512KX8: ASSEMBLY: USB3_TYPEA; CDS_LIB: memory; CDS_PART_NAME: U_MEM_FL_SER_512KX8_SO_8-104MHZ,2.3V..3.6V,W25X40CLSNIG,170-0285-000; CDS_PHYS_PART_NAME: U_MEM_FL_SER_512KX8_SO_8-104MHZ,2.3V..3.6V,W25X40CLSNIG,170-0285-000-170-0285-000; CDS_SEC: 1; DEVICE_TYPENAME: U_MEM_FL_SER_512KX8_SO_8-104MHZ23V36VW25X40CLSNIG170-0285-000-170-0285-000; DRAWING: #NAME?; NV_NAME: W25X40CLSNIG; NV_PN: 170-0285-000; PACK_TYPE: SO_8; PATH: I198; PHYS_PAGE: 13; POW: 2.3V..3.6V; ROT: 0; SEC: 1; SPEED_GRADE: 104MHz; VER: 1; XY: (-9800,2950)
VS1 = VIRTUAL_SHORT: ASSEMBLY: USB3_TYPEA; CDS_LIB: mechanic; CDS_PART_NAME: VIRTUAL_SHORT_SHUNT-VIRTUAL_SHORT; CDS_PHYS_PART_NAME: VIRTUAL_SHORT_SHUNT-VIRTUAL_SHORT; CDS_SEC: 1; DEVICE_TYPENAME: VIRTUAL_SHORT_SHUNT-VIRTUAL_SHORT; DRAWING: #NAME?; PACK_TYPE: SHUNT; PATH: I80; PHYS_PAGE: 13; ROT: 0; SEC: 1; VER: 1; XY: (-10450,7050)
VS2 = VIRTUAL_SHORT: ASSEMBLY: USB3_TYPEA; CDS_LIB: mechanic; CDS_PART_NAME: VIRTUAL_SHORT_SHUNT-VIRTUAL_SHORT; CDS_PHYS_PART_NAME: VIRTUAL_SHORT_SHUNT-VIRTUAL_SHORT; CDS_SEC: 1; DEVICE_TYPENAME: VIRTUAL_SHORT_SHUNT-VIRTUAL_SHORT; DRAWING: #NAME?; PACK_TYPE: SHUNT; PATH: I81; PHYS_PAGE: 13; ROT: 0; SEC: 1; VER: 1; XY: (-10450,6900)
VS3 = VIRTUAL_SHORT: ASSEMBLY: USB3_TYPEA; CDS_LIB: mechanic; CDS_PART_NAME: VIRTUAL_SHORT_SHUNT-VIRTUAL_SHORT; CDS_PHYS_PART_NAME: VIRTUAL_SHORT_SHUNT-VIRTUAL_SHORT; CDS_SEC: 1; DEVICE_TYPENAME: VIRTUAL_SHORT_SHUNT-VIRTUAL_SHORT; DRAWING: #NAME?; PACK_TYPE: SHUNT; PATH: I82; PHYS_PAGE: 13; ROT: 0; SEC: 1; VER: 1; XY: (-10450,6750)
VS4 = VIRTUAL_SHORT: ASSEMBLY: USB3_TYPEA; CDS_LIB: mechanic; CDS_PART_NAME: VIRTUAL_SHORT_SHUNT-VIRTUAL_SHORT; CDS_PHYS_PART_NAME: VIRTUAL_SHORT_SHUNT-VIRTUAL_SHORT; CDS_SEC: 1; DEVICE_TYPENAME: VIRTUAL_SHORT_SHUNT-VIRTUAL_SHORT; DRAWING: #NAME?; PACK_TYPE: SHUNT; PATH: I83; PHYS_PAGE: 13; ROT: 0; SEC: 1; VER: 1; XY: (-10450,6600)
VS5 = VIRTUAL_SHORT: ASSEMBLY: USB3_TYPEA; CDS_LIB: mechanic; CDS_PART_NAME: VIRTUAL_SHORT_SHUNT-VIRTUAL_SHORT; CDS_PHYS_PART_NAME: VIRTUAL_SHORT_SHUNT-VIRTUAL_SHORT; CDS_SEC: 1; DEVICE_TYPENAME: VIRTUAL_SHORT_SHUNT-VIRTUAL_SHORT; DRAWING: #NAME?; PACK_TYPE: SHUNT; PATH: I84; PHYS_PAGE: 13; ROT: 0; SEC: 1; VER: 1; XY: (-10450,6450)
VS6 = VIRTUAL_SHORT: ASSEMBLY: USB3_TYPEA; CDS_LIB: mechanic; CDS_PART_NAME: VIRTUAL_SHORT_SHUNT-VIRTUAL_SHORT; CDS_PHYS_PART_NAME: VIRTUAL_SHORT_SHUNT-VIRTUAL_SHORT; CDS_SEC: 1; DEVICE_TYPENAME: VIRTUAL_SHORT_SHUNT-VIRTUAL_SHORT; DRAWING: #NAME?; PACK_TYPE: SHUNT; PATH: I86; PHYS_PAGE: 13; ROT: 0; SEC: 1; VER: 1; XY: (-10450,6300)
VS7 = VIRTUAL_SHORT: ASSEMBLY: USB3_TYPEA; CDS_LIB: mechanic; CDS_PART_NAME: VIRTUAL_SHORT_SHUNT-VIRTUAL_SHORT; CDS_PHYS_PART_NAME: VIRTUAL_SHORT_SHUNT-VIRTUAL_SHORT; CDS_SEC: 1; DEVICE_TYPENAME: VIRTUAL_SHORT_SHUNT-VIRTUAL_SHORT; DRAWING: #NAME?; PACK_TYPE: SHUNT; PATH: I88; PHYS_PAGE: 13; ROT: 0; SEC: 1; VER: 1; XY: (-10450,6150)
VS8 = VIRTUAL_SHORT: ASSEMBLY: USB3_TYPEA; CDS_LIB: mechanic; CDS_PART_NAME: VIRTUAL_SHORT_SHUNT-VIRTUAL_SHORT; CDS_PHYS_PART_NAME: VIRTUAL_SHORT_SHUNT-VIRTUAL_SHORT; CDS_SEC: 1; DEVICE_TYPENAME: VIRTUAL_SHORT_SHUNT-VIRTUAL_SHORT; DRAWING: #NAME?; PACK_TYPE: SHUNT; PATH: I87; PHYS_PAGE: 13; ROT: 0; SEC: 1; VER: 1; XY: (-10450,6000)
VS9 = VIRTUAL_SHORT: ASSEMBLY: USB3_TYPEA; CDS_LIB: mechanic; CDS_PART_NAME: VIRTUAL_SHORT_SHUNT-VIRTUAL_SHORT; CDS_PHYS_PART_NAME: VIRTUAL_SHORT_SHUNT-VIRTUAL_SHORT; CDS_SEC: 1; DEVICE_TYPENAME: VIRTUAL_SHORT_SHUNT-VIRTUAL_SHORT; DRAWING: #NAME?; PACK_TYPE: SHUNT; PATH: I89; PHYS_PAGE: 13; ROT: 0; SEC: 1; VER: 1; XY: (-10450,5150)
VS10 = VIRTUAL_SHORT: ASSEMBLY: USB3_TYPEA; CDS_LIB: mechanic; CDS_PART_NAME: VIRTUAL_SHORT_SHUNT-VIRTUAL_SHORT; CDS_PHYS_PART_NAME: VIRTUAL_SHORT_SHUNT-VIRTUAL_SHORT; CDS_SEC: 1; DEVICE_TYPENAME: VIRTUAL_SHORT_SHUNT-VIRTUAL_SHORT; DRAWING: #NAME?; PACK_TYPE: SHUNT; PATH: I90; PHYS_PAGE: 13; ROT: 0; SEC: 1; VER: 1; XY: (-10450,5000)
VS12 = VIRTUAL_SHORT: ASSEMBLY: USB3_TYPEA; CDS_LIB: mechanic; CDS_PART_NAME: VIRTUAL_SHORT_SHUNT-VIRTUAL_SHORT; CDS_PHYS_PART_NAME: VIRTUAL_SHORT_SHUNT-VIRTUAL_SHORT; CDS_SEC: 1; DEVICE_TYPENAME: VIRTUAL_SHORT_SHUNT-VIRTUAL_SHORT; DRAWING: #NAME?; PACK_TYPE: SHUNT; PATH: I93; PHYS_PAGE: 13; ROT: 0; SEC: 1; VER: 1; XY: (-10450,4400)
VS13 = VIRTUAL_SHORT: ASSEMBLY: USB3_TYPEA; CDS_LIB: mechanic; CDS_PART_NAME: VIRTUAL_SHORT_SHUNT-VIRTUAL_SHORT; CDS_PHYS_PART_NAME: VIRTUAL_SHORT_SHUNT-VIRTUAL_SHORT; CDS_SEC: 1; DEVICE_TYPENAME: VIRTUAL_SHORT_SHUNT-VIRTUAL_SHORT; DRAWING: #NAME?; PACK_TYPE: SHUNT; PATH: I94; PHYS_PAGE: 13; ROT: 0; SEC: 1; VER: 1; XY: (-10450,4250)
VS17 = VIRTUAL_SHORT: ASSEMBLY: USB3_TYPEA; CDS_LIB: mechanic; CDS_PART_NAME: VIRTUAL_SHORT_SHUNT-VIRTUAL_SHORT; CDS_PHYS_PART_NAME: VIRTUAL_SHORT_SHUNT-VIRTUAL_SHORT; CDS_SEC: 1; DEVICE_TYPENAME: VIRTUAL_SHORT_SHUNT-VIRTUAL_SHORT; DRAWING: #NAME?; PACK_TYPE: SHUNT; PATH: I147; PHYS_PAGE: 13; ROT: 0; SEC: 1; VER: 1; XY: (-10450,5850)
VS18 = VIRTUAL_SHORT: ASSEMBLY: USB3_TYPEA; CDS_LIB: mechanic; CDS_PART_NAME: VIRTUAL_SHORT_SHUNT-VIRTUAL_SHORT; CDS_PHYS_PART_NAME: VIRTUAL_SHORT_SHUNT-VIRTUAL_SHORT; CDS_SEC: 1; DEVICE_TYPENAME: VIRTUAL_SHORT_SHUNT-VIRTUAL_SHORT; DRAWING: #NAME?; PACK_TYPE: SHUNT; PATH: I148; PHYS_PAGE: 13; ROT: 0; SEC: 1; VER: 1; XY: (-10450,5700)
Y1 = XTAL_4PIN: ASSEMBLY: USB3_TYPEA; CDS_LIB: clocks; CDS_PART_NAME: XTAL_4PIN_SMD_32X25-7M12070053,12MHZ,15PPM,2PPM,35PPM,10PF,FUNDAMENTAL,085-0347-000; CDS_PHYS_PART_NAME: XTAL_4PIN_SMD_32X25-7M12070053,12MHZ,15PPM,2PPM,35PPM,10PF,FUNDAMENTAL,085-0347-000-085-0347-000,12MHZ; CDS_SEC: 1; DEVICE_TYPENAME: XTAL_4PIN_SMD_32X25-7M1207005312MHZ15PPM2PPM35PPM10PFFUNDAMENTAL085-0347-000-085-0347-00012MHZ; DRAWING: #NAME?; LOAD_CAPACITANCE: 10pF; NV_NAME: 7M12070053; NV_PN: 085-0347-000; OVERTONE: Fundamental; PACK_TYPE: SMD_32X25; PATH: I10; PHYS_PAGE: 13; ROT: 0; SEC: 1; TOL: 15ppm; TOL_AGE: 2ppm; TOL_TOTAL: 35ppm; VER: 2; XY: (-2350,5250)

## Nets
5V_LDO: C51.1 C52.1 U7.41(5V_LDO) VS12.2(B) VS13.2(B)
AV10_1: C40.1 U7.1(AV10) VS1.2(B)
AV10_2: C41.1 U7.7(AV10_2) VS2.2(B)
AV10_3: C42.1 U7.16(AV10_3) VS3.2(B)
AV10_4: C43.1 U7.23(AV10_4) VS4.2(B)
AV10_5: C44.1 U7.29(AV10_5) VS5.2(B)
AV10_6: C45.1 U7.35(AV10_6) VS6.2(B)
AV10_7: C46.1 U7.46(AV10_7) VS7.2(B)
AV10_8: C47.1 U7.57(AV10_8) VS8.2(B)
AV10_9: C155.1 U7.72(AV10_9) VS17.2(B)
AV10_10: C156.1 U7.81(AV10_10) VS18.2(B)
AV33_2: C48.1 U7.42(AV33_2) VS9.2(B)
AV33_3: C49.1 U7.85(AV33_3) VS10.2(B)
GND: C38.2 C39.2 C40.2 C41.2 C42.2 C43.2 C44.2 C45.2 C46.2 C47.2 C48.2 C49.2 C51.2 C52.2 C55.2 C56.2 C58.2 C61.2 C63.1 C155.2 C156.2 C163.2 C164.2 C166.2 C167.2 C170.2 D5.2 D6.2 D7.2 J5.5(GND) J5.6(SH1) J5.7(SH2) J5.8(SH3) J5.9(SH4) Q8.2(S) R33.2 R35.1 R175.2 R178.2 U7.4(GND1) U7.26(GND2) U7.32(GND3) U7.89(EPAD) U26.1(GND) U28.4(GND) Y1.2 Y1.4 ; also on sheet 1 2 3 4 5 6 7 8 9 10 11 14 15 16 17 18 19 21
VDD_3V3_SYS: C56.1 C58.1 C170.1 R36.1 R37.1 R38.1 R199.1 R200.1 R201.1 U7.22(AV33_1) U28.8(VCC) VS9.1(A) VS10.1(A) VS12.1(A) VS13.1(A) ; also on sheet 2 3 4 5 6 7 8 9 15 16 19 20 21
VDD_5V_SYS: C163.1 C164.1 U26.3(VIN) ; also on sheet 2 3 8 9 10 11 14 15 16 17 21
VDD_AV10_HUB: C166.1 C167.1 L19.2 R176.1 U26.6(OUT) VS1.1(A) VS2.1(A) VS3.1(A) VS4.1(A) VS5.1(A) VS6.1(A) VS7.1(A) VS8.1(A) VS17.1(A) VS18.1(A)
BUCK_1V1_FB: C165.2 R177.2 R178.1 U26.5(FB)
BUCK_1V1_FB_MID: C165.1 R176.2 R177.1
BUCK_1V1_SW: L19.1 U26.2(SW)
BUCK_3V3_PG: R175.1 U26.4(EN) ; also on sheet 8 14 15 16
CAM_I2C_SCL: U7.69(SM_CLK) ; also on sheet 7 20
CAM_I2C_SDA: U7.70(SM_DAT) ; also on sheet 7 20
DSP1_DN: U7.50(DSP1_D_N) ; also on sheet 11
DSP1_DP: U7.49(DSP1_D_P) ; also on sheet 11
DSP1_SSRX_N: U7.8(DSP1_RX_N) ; also on sheet 11
DSP1_SSRX_P: U7.9(DSP1_RX_P) ; also on sheet 11
DSP1_SSTX_N: U7.13(DSP1_TX_N) ; also on sheet 11
DSP1_SSTX_P: U7.12(DSP1_TX_P) ; also on sheet 11
DSP2_DN: U7.52(DSP2_D_N) ; also on sheet 11
DSP2_DP: U7.51(DSP2_D_P) ; also on sheet 11
DSP2_SSRX_N: U7.2(DSP2_RX_N) ; also on sheet 11
DSP2_SSRX_P: U7.3(DSP2_RX_P) ; also on sheet 11
DSP2_SSTX_N: U7.6(DSP2_TX_N) ; also on sheet 11
DSP2_SSTX_P: U7.5(DSP2_TX_P) ; also on sheet 11
DSP3_DN: U7.54(DSP3_D_N) ; also on sheet 10
DSP3_DP: U7.53(DSP3_D_P) ; also on sheet 10
DSP3_SSRX_N: U7.30(DSP3_RX_N) ; also on sheet 10
DSP3_SSRX_P: U7.31(DSP3_RX_P) ; also on sheet 10
DSP3_SSTX_N: U7.34(DSP3_TX_N) ; also on sheet 10
DSP3_SSTX_P: U7.33(DSP3_TX_P) ; also on sheet 10
DSP4_DN: U7.56(DSP4_D_N) ; also on sheet 10
DSP4_DP: U7.55(DSP4_D_P) ; also on sheet 10
DSP4_SSRX_N: U7.24(DSP4_RX_N) ; also on sheet 10
DSP4_SSRX_P: U7.25(DSP4_RX_P) ; also on sheet 10
DSP4_SSTX_N: U7.28(DSP4_TX_N) ; also on sheet 10
DSP4_SSTX_P: U7.27(DSP4_TX_P) ; also on sheet 10
HUB_ADC_CAP: C55.1 U7.40(ADC_CAP)
HUB_DSP12_OCP: R38.2 U7.21(DSP1_OCP) U7.62(DSP2_OCP) ; also on sheet 11
HUB_DSP12_PWR_EN: U7.19(DSP1_PWR_EN) U7.64(DSP2_PWR_EN) ; also on sheet 11
HUB_DSP34_OCP: R36.2 U7.20(DSP3_OCP) U7.63(DSP4_OCP) ; also on sheet 10
HUB_DSP34_PWR_EN: U7.18(DSP3_PWR_EN) U7.65(DSP4_PWR_EN) ; also on sheet 10
HUB_PWR_DET: R37.2 U7.36(BPWR_DET) U7.39(LOC_PWR)
HUB_XTAL_IN: C61.1 U7.43(XTLI) Y1.1
HUB_XTAL_OUT: C63.2 U7.44(XTLO) Y1.3
MICRO_USB_VBUS_DET: C38.1 C39.1 D5.1 J5.1(VBUS) R32.1
RREF: R35.2 U7.45(RREF)
SNN_5V_IN1: U7.83(5V_IN1)
SNN_5V_IN2: U7.87(5V_IN2)
SNN_HUB_ADC_IN0: U7.37(ADC_IN0)
SNN_HUB_ADC_IN1: U7.38(ADC_IN1)
SNN_HUB_GPIO14: U7.71(GPIO14)
SNN_HUB_I2C_CLK: U7.17(I2C_CLK)
SNN_HUB_I2C_DAT: U7.66(I2C_DAT)
SNN_HUB_I2C_INT#: U7.67(I2C_INT*)
SNN_HUB_NC01: U7.10(NC1)
SNN_HUB_NC02: U7.11(NC2)
SNN_HUB_NC03: U7.14(NC3)
SNN_HUB_NC04: U7.15(NC4)
SNN_HUB_NC05: U7.75(NC5)
SNN_HUB_NC06: U7.76(NC6)
SNN_HUB_NC07: U7.79(NC7)
SNN_HUB_NC08: U7.80(NC8)
SNN_HUB_NC09: U7.82(NC9)
SNN_HUB_NC10: U7.84(NC10)
SNN_HUB_NC11: U7.86(NC11)
SNN_HUB_NC12: U7.88(NC12)
SNN_HUB_SM_INT#: U7.68(SM_INT*)
SNN_USB0_ID_CONN: J5.4(ID)
SPI_FL_HLD: R201.2 U28.7(HOLD*)
SPI_FL_WP: R200.2 U28.3(WP*)
SPI_HUB_CS: R199.2 U7.61(SPI_SCS_N) U28.1(CS*)
SPI_HUB_MISO: U7.58(SPI_MISO) U28.2(DO)
SPI_HUB_MOSI: U7.59(SPI_MOSI) U28.5(DIO)
SPI_HUB_SCK: U7.60(SPI_SCK) U28.6(CLK)
USB0_AP_N: D7.1 J5.2(DN) ; also on sheet 20
USB0_AP_P: D6.1 J5.3(DP) ; also on sheet 20
USB0_VBUS_DET: Q8.1(G) R32.2 R33.1
USB0_VBUS_DET*: Q8.3(D) ; also on sheet 20
USB1_AP_N: U7.48(USP_D_N) ; also on sheet 20
USB1_AP_P: U7.47(USP_D_P) ; also on sheet 20
USBSS_RX_HUB_N: C62.2 U7.73(USP_RX_N)
USBSS_RX_HUB_P: C60.2 U7.74(USP_RX_P)
USBSS_TX_HUB_N: U7.78(USP_TX_N) ; also on sheet 19
USBSS_TX_HUB_P: U7.77(USP_TX_P) ; also on sheet 19
USBSS_TX_N: C62.1 ; also on sheet 19
USBSS_TX_P: C60.1 ; also on sheet 19

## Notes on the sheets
sheet 12
- A
- B
- C
- D
- E
- F
- G
- H
- DECOUPLING CAPS
- USB3.1 GEN2 HUB x4 PORTS
- 1V1 DCDC FOR USB HUB
- PULL-UP FOR OCP
- POWER ON/OFF CONTROL
- 1
- 1
- FOR AV10 PINS
- SELF POWER DETECTION
- 12MHz CRYSTAL FOR RTS5411S SYSTEM CLOCK
- Vin_H > 1.2V
- VOUT=(0.6V)/ (Rb/(Rt+Rb))
- Rt
- Rt=100k
- Rb=121k
- VOUT=1.095V
- 2
- Rb
- 2
- FOR AV33 PINS
- FOR 5V_LDO PIN
- 3
- 3
- SPI FLASH FOR RTS5489
- 4
- 4
- 5
- 5
- I2C slave addrs: 7'1101010b = 7'h6A
- NVIDIA CORPORATION
- 2701 SAN TOMAS EXPRESSWAY
- ASSEMBLY
- <ASSEMBLY_DESCRIPTION>
- SANTA CLARA, CA 95050, USA
- PAGE DETAIL
- USB3.1 HUB
- NV_PN
- 600-13509-BASE-100
- ALL NVIDIA DESIGN SPECIFICATIONS, REFERENCE SPECIFICATIONS, REFERENCE BOARDS, FILES, DRAWINGS, DIAGNOSTICS, LISTS AND OTHER DOCUMENTS OR INFORMATION (TOGETHER AND SEPARATELY, 'MATERIALS') ARE BEING PROVIDED 'AS IS'. THE MATERIALS MAY
- CONTAIN KNOWN AND UNKNOWN VIOLATIONS OR DEVIATIONS OF INDUSTRY STANDARDS AND SPECIFICATIONS. NVIDIA MAKES NO WARRANTIES, EXPRESSED, IMPLIED, STATUTORY OR OTHERWISE WITH RESPECT TO THE MATERIALS OR OTHERWISE, AND EXPRESSLY DISCLAIMS ALL
- PCB REV
- P3509-A01
- PAGE
- 13 OF 25
- IMPLIED WARRANTIES INCLUDING, WITHOUT LIMITATION, THE WARRANTIES OF DESIGN, OF NONINFRINGEMENT, MERCHANTABILITY OR FITNESS FOR A PARTICULAR PURPOSE, OR ARISING FROM A COURSE OF DEALING, TRADE USAGE, TRADE PRACTICE, OR INDUSTRY STANDARDS.
- BOM REV
- <BOM_REV>
- DATE
- 27-NOV-2019
- A
- B
- C
- D
- E
- F
- G
- H
sheet 13
- A
- B
- C
- D
- E
- F
- G
- H
- MICRO USB (DEVICE MODE ONLY)
- 1
- 1
- 2
- 2
- 3
- 3
- 4
- 4
- 5
- 5
- NVIDIA CORPORATION
- 2701 SAN TOMAS EXPRESSWAY
- ASSEMBLY
- <ASSEMBLY_DESCRIPTION>
- SANTA CLARA, CA 95050, USA
- PAGE DETAIL
- MICRO USB2.0
- NV_PN
- 600-13509-BASE-100
- ALL NVIDIA DESIGN SPECIFICATIONS, REFERENCE SPECIFICATIONS, REFERENCE BOARDS, FILES, DRAWINGS, DIAGNOSTICS, LISTS AND OTHER DOCUMENTS OR INFORMATION (TOGETHER AND SEPARATELY, 'MATERIALS') ARE BEING PROVIDED 'AS IS'. THE MATERIALS MAY
- CONTAIN KNOWN AND UNKNOWN VIOLATIONS OR DEVIATIONS OF INDUSTRY STANDARDS AND SPECIFICATIONS. NVIDIA MAKES NO WARRANTIES, EXPRESSED, IMPLIED, STATUTORY OR OTHERWISE WITH RESPECT TO THE MATERIALS OR OTHERWISE, AND EXPRESSLY DISCLAIMS ALL
- PCB REV
- P3509-A01
- PAGE
- 12 OF 25
- IMPLIED WARRANTIES INCLUDING, WITHOUT LIMITATION, THE WARRANTIES OF DESIGN, OF NONINFRINGEMENT, MERCHANTABILITY OR FITNESS FOR A PARTICULAR PURPOSE, OR ARISING FROM A COURSE OF DEALING, TRADE USAGE, TRADE PRACTICE, OR INDUSTRY STANDARDS.
- BOM REV
- <BOM_REV>
- DATE
- 27-NOV-2019
- A
- B
- C
- D
- E
- F
- G
- H
